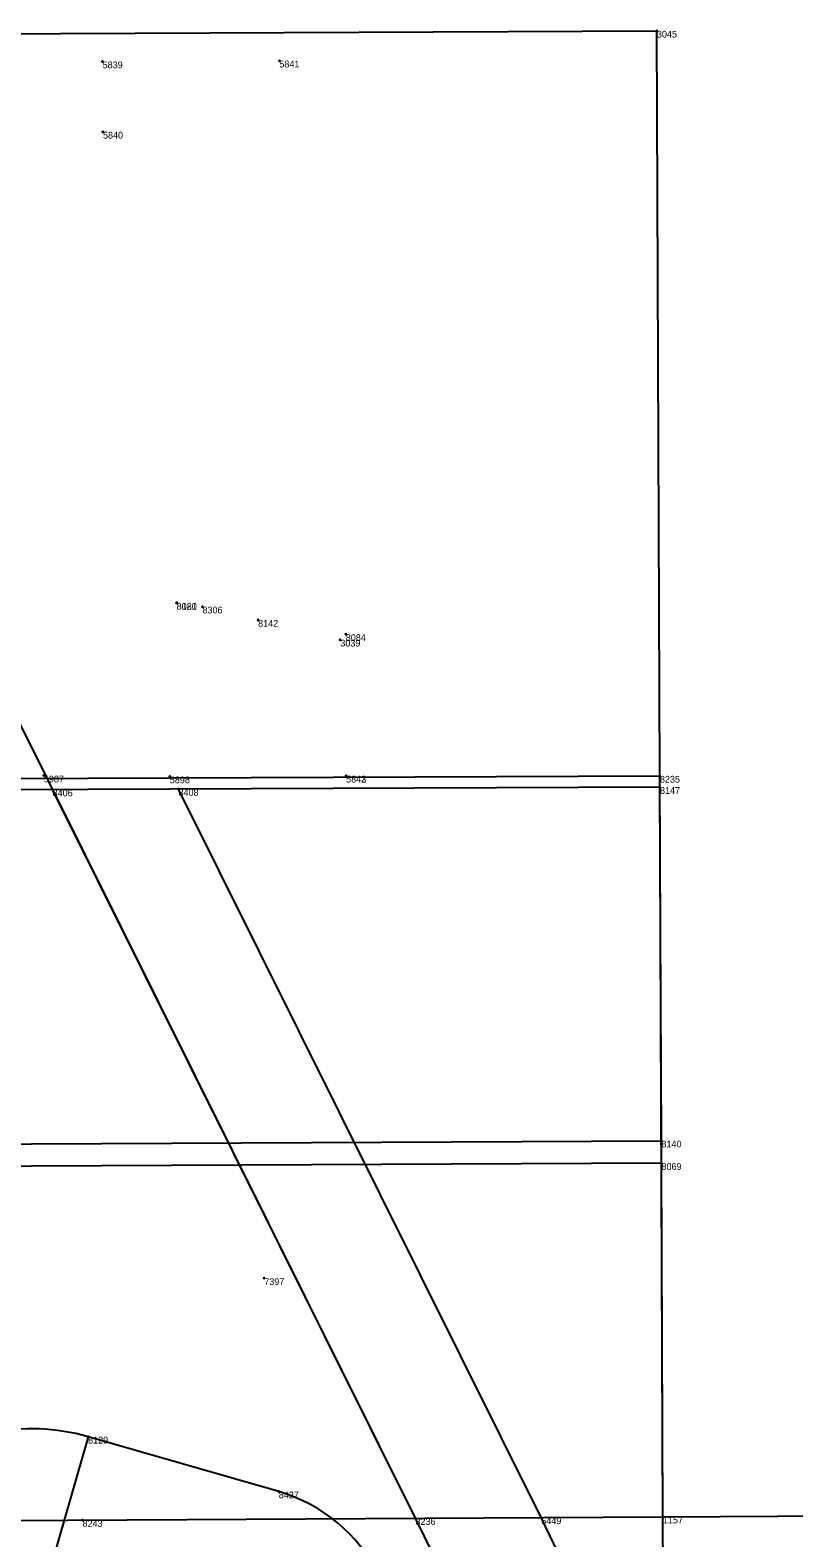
# Model space of a CAD drawing. Extents: x 2145146 to 2158053, y 137507 to 150829.
# Drawn here: x 2152428 to 2153788, y 145617 to 148298 of the extents above; entities that cross this region are included whole.
import ezdxf

# ---------------------------------------------------------------- set-up
doc = ezdxf.new("R2010")
doc.units = 0
for name, color, linetype in [('ALIGN_Cogo Points', 7, 'Continuous'), ('ALIGN_ROW Line', 7, 'Continuous'), ('PLSS_Block Line', 7, 'Continuous'), ('PLSS_Property Line', 7, 'Continuous'), ('PLSS_Section Line', 7, 'Continuous')]:
    doc.layers.add(name, color=color, linetype=linetype)

msp = doc.modelspace()

# ---------------------------------------------------------------- linework, layer by layer
at = {"layer": 'ALIGN_Cogo Points'}
for points in [[(2153544, 148296.8), (2153544, 148298), (2153544, 148296.8), (2153542.8, 148296.8), (2153544, 148296.8), (2153544, 148295.6), (2153544, 148296.8), (2153545.2, 148296.8)], [(2152557.5, 148242.2), (2152557.5, 148243.4), (2152557.5, 148242.2), (2152556.3, 148242.2), (2152557.5, 148242.2), (2152557.5, 148241), (2152557.5, 148242.2), (2152558.7, 148242.2)], [(2152872, 148243.7), (2152872, 148244.9), (2152872, 148243.7), (2152870.8, 148243.7), (2152872, 148243.7), (2152872, 148242.5), (2152872, 148243.7), (2152873.2, 148243.7)], [(2152558.1, 148117.2), (2152558.1, 148118.4), (2152558.1, 148117.2), (2152556.9, 148117.2), (2152558.1, 148117.2), (2152558.1, 148116), (2152558.1, 148117.2), (2152559.3, 148117.2)], [(2152689.1, 147279.5), (2152689.1, 147280.7), (2152689.1, 147279.5), (2152687.9, 147279.5), (2152689.1, 147279.5), (2152689.1, 147278.3), (2152689.1, 147279.5), (2152690.3, 147279.5)], [(2152689.3, 147279.4), (2152689.3, 147280.6), (2152689.3, 147279.4), (2152688.1, 147279.4), (2152689.3, 147279.4), (2152689.3, 147278.2), (2152689.3, 147279.4), (2152690.5, 147279.4)], [(2152735.1, 147272.7), (2152735.1, 147273.9), (2152735.1, 147272.7), (2152733.9, 147272.7), (2152735.1, 147272.7), (2152735.1, 147271.5), (2152735.1, 147272.7), (2152736.3, 147272.7)], [(2152834.2, 147249), (2152834.2, 147250.2), (2152834.2, 147249), (2152833, 147249), (2152834.2, 147249), (2152834.2, 147247.8), (2152834.2, 147249), (2152835.4, 147249)], [(2152980.5, 147213.9), (2152980.5, 147215.1), (2152980.5, 147213.9), (2152979.3, 147213.9), (2152980.5, 147213.9), (2152980.5, 147212.7), (2152980.5, 147213.9), (2152981.7, 147213.9)], [(2152990.2, 147223.7), (2152990.2, 147224.9), (2152990.2, 147223.7), (2152989, 147223.7), (2152990.2, 147223.7), (2152990.2, 147222.5), (2152990.2, 147223.7), (2152991.4, 147223.7)], [(2152452.9, 146972.2), (2152452.9, 146973.4), (2152452.9, 146972.2), (2152451.7, 146972.2), (2152452.9, 146972.2), (2152452.9, 146971), (2152452.9, 146972.2), (2152454.1, 146972.2)], [(2152677, 146970.6), (2152677, 146971.8), (2152677, 146970.6), (2152675.8, 146970.6), (2152677, 146970.6), (2152677, 146969.4), (2152677, 146970.6), (2152678.2, 146970.6)], [(2152990.8, 146972), (2152990.8, 146973.2), (2152990.8, 146972), (2152989.6, 146972), (2152990.8, 146972), (2152990.8, 146970.8), (2152990.8, 146972), (2152992, 146972)], [(2152990.8, 146972), (2152990.8, 146973.2), (2152990.8, 146972), (2152989.6, 146972), (2152990.8, 146972), (2152990.8, 146970.8), (2152990.8, 146972), (2152992, 146972)], [(2153549.3, 146971.8), (2153549.3, 146973), (2153549.3, 146971.8), (2153548.1, 146971.8), (2153549.3, 146971.8), (2153549.3, 146970.6), (2153549.3, 146971.8), (2153550.5, 146971.8)], [(2152468.5, 146947.5), (2152468.5, 146948.7), (2152468.5, 146947.5), (2152467.3, 146947.5), (2152468.5, 146947.5), (2152468.5, 146946.3), (2152468.5, 146947.5), (2152469.7, 146947.5)], [(2152692.5, 146948.3), (2152692.5, 146949.5), (2152692.5, 146948.3), (2152691.3, 146948.3), (2152692.5, 146948.3), (2152692.5, 146947.1), (2152692.5, 146948.3), (2152693.7, 146948.3)], [(2153549.4, 146951.8), (2153549.4, 146953), (2153549.4, 146951.8), (2153548.2, 146951.8), (2153549.4, 146951.8), (2153549.4, 146950.6), (2153549.4, 146951.8), (2153550.6, 146951.8)], [(2153552, 146323), (2153552, 146324.2), (2153552, 146323), (2153550.8, 146323), (2153552, 146323), (2153552, 146321.8), (2153552, 146323), (2153553.2, 146323)], [(2153552.1, 146283), (2153552.1, 146284.2), (2153552.1, 146283), (2153550.9, 146283), (2153552.1, 146283), (2153552.1, 146281.8), (2153552.1, 146283), (2153553.3, 146283)], [(2152845.1, 146078.3), (2152845.1, 146079.5), (2152845.1, 146078.3), (2152843.9, 146078.3), (2152845.1, 146078.3), (2152845.1, 146077.1), (2152845.1, 146078.3), (2152846.3, 146078.3)], [(2152531.6, 145796.4), (2152531.6, 145797.6), (2152531.6, 145796.4), (2152530.4, 145796.4), (2152531.6, 145796.4), (2152531.6, 145795.2), (2152531.6, 145796.4), (2152532.8, 145796.4)], [(2152870.9, 145699), (2152870.9, 145700.2), (2152870.9, 145699), (2152869.7, 145699), (2152870.9, 145699), (2152870.9, 145697.8), (2152870.9, 145699), (2152872.1, 145699)], [(2153114.2, 145651.7), (2153114.2, 145652.9), (2153114.2, 145651.7), (2153113, 145651.7), (2153114.2, 145651.7), (2153114.2, 145650.5), (2153114.2, 145651.7), (2153115.4, 145651.7)], [(2153338.2, 145653), (2153338.2, 145654.2), (2153338.2, 145653), (2153337, 145653), (2153338.2, 145653), (2153338.2, 145651.8), (2153338.2, 145653), (2153339.4, 145653)], [(2153554.7, 145654.3), (2153554.7, 145655.5), (2153554.7, 145654.3), (2153553.5, 145654.3), (2153554.7, 145654.3), (2153554.7, 145653.1), (2153554.7, 145654.3), (2153555.9, 145654.3)], [(2152521.7, 145648.3), (2152521.7, 145649.5), (2152521.7, 145648.3), (2152520.5, 145648.3), (2152521.7, 145648.3), (2152521.7, 145647.1), (2152521.7, 145648.3), (2152522.9, 145648.3)]]:
    msp.add_lwpolyline(points, dxfattribs=at)
at = {"layer": 'ALIGN_ROW Line'}
for points in [[(2153114.2, 145651.7), (2151939.7, 148008.6)], [(2153114.2, 145651.7), (2152468.5, 146947.5)], [(2153338.2, 145653), (2152692.5, 146948.3)], [(2153599.9, 144662.6), (2153114.2, 145651.7)], [(2153781.4, 144748.3), (2153781.4, 144748.3), (2153557.8, 145195.9), (2153338.2, 145653)]]:
    msp.add_lwpolyline(points, dxfattribs=at)
msp.add_arc((2152431.8, 145449), 361.5, 73.9727, 129.7426, dxfattribs=at)
at = {"layer": 'PLSS_Block Line'}
for points in [[(2150931, 146961.3), (2153549.3, 146971.8)], [(2153554.7, 145654.3), (2153552.1, 146283), (2153552, 146323), (2153549.4, 146951.8), (2153549.3, 146971.8)], [(2153549.4, 146951.8), (2150931.1, 146941.3)], [(2150934.9, 146310.3), (2153552, 146323)], [(2153552.1, 146283), (2150935.2, 146270.3)]]:
    msp.add_lwpolyline(points, dxfattribs=at)
at = {"layer": 'PLSS_Property Line'}
msp.add_lwpolyline([(2152870.9, 145699), (2152870.9, 145699), (2152531.6, 145796.4), (2152448.8, 145508), (2152450.5, 145181.5), (2152296.2, 145180.7), (2152297.7, 144904.8), (2152369, 144834.2), (2152763.9, 144836.2), (2152765.8, 144468.4), (2152790.9, 144443.5), (2152791.4, 144359.7), (2152585.3, 144358.6), (2152560.2, 144383.4), (2152560, 144413.4), (2152243.4, 144411.8), (2152211, 144379), (2152211.5, 144277.6), (2152191.7, 144277.5), (2152193.9, 143760.5), (2152292.1, 143739.4), (2152358.2, 143726.6)], dxfattribs=at)
msp.add_arc((2152791.8, 145423.6), 286.5, 26.4414, 73.9775, dxfattribs=at)
at = {"layer": 'PLSS_Section Line'}
for points in [[(2150890, 148284.8), (2153544, 148296.8)], [(2153554.7, 145654.3), (2153544, 148296.8)], [(2150905.8, 145639), (2153554.7, 145654.3)], [(2153554.7, 145654.3), (2156207, 145669.7)], [(2153570, 143016.2), (2153554.7, 145654.3)]]:
    msp.add_lwpolyline(points, dxfattribs=at)

# ---------------------------------------------------------------- texts
at = {"layer": 'ALIGN_Cogo Points'}
for s, p in [('3045', (2153544, 148284.8)), ('5839', (2152557.5, 148230.2)), ('5841', (2152872, 148231.7)), ('5840', (2152558.1, 148105.2)), ('8121', (2152689.1, 147267.5)), ('8080', (2152689.3, 147267.4)), ('8306', (2152735.1, 147260.7)), ('8142', (2152834.2, 147237)), ('3039', (2152980.5, 147201.9)), ('8084', (2152990.2, 147211.7)), ('5987', (2152452.9, 146960.2)), ('5898', (2152677, 146958.6)), ('5842', (2152990.8, 146960)), ('5843', (2152990.8, 146960)), ('8235', (2153549.3, 146959.8)), ('8406', (2152468.5, 146935.5)), ('8408', (2152692.5, 146936.3)), ('8147', (2153549.4, 146939.8)), ('8140', (2153552, 146311)), ('8069', (2153552.1, 146271)), ('7397', (2152845.1, 146066.3)), ('8129', (2152531.6, 145784.4)), ('8427', (2152870.9, 145687)), ('8236', (2153114.2, 145639.7)), ('5449', (2153338.2, 145641)), ('1157', (2153554.7, 145642.3)), ('8243', (2152521.7, 145636.3))]:
    msp.add_text(s, height=12, dxfattribs=at).set_placement(p)

doc.saveas('drawing.dxf')
